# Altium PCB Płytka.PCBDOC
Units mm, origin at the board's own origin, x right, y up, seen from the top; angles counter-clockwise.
Board outline 97 x 97 mm, 2 copper layers (TopLayer, BottomLayer); 28 components, 0 nets, 155 pads, 1 vias.
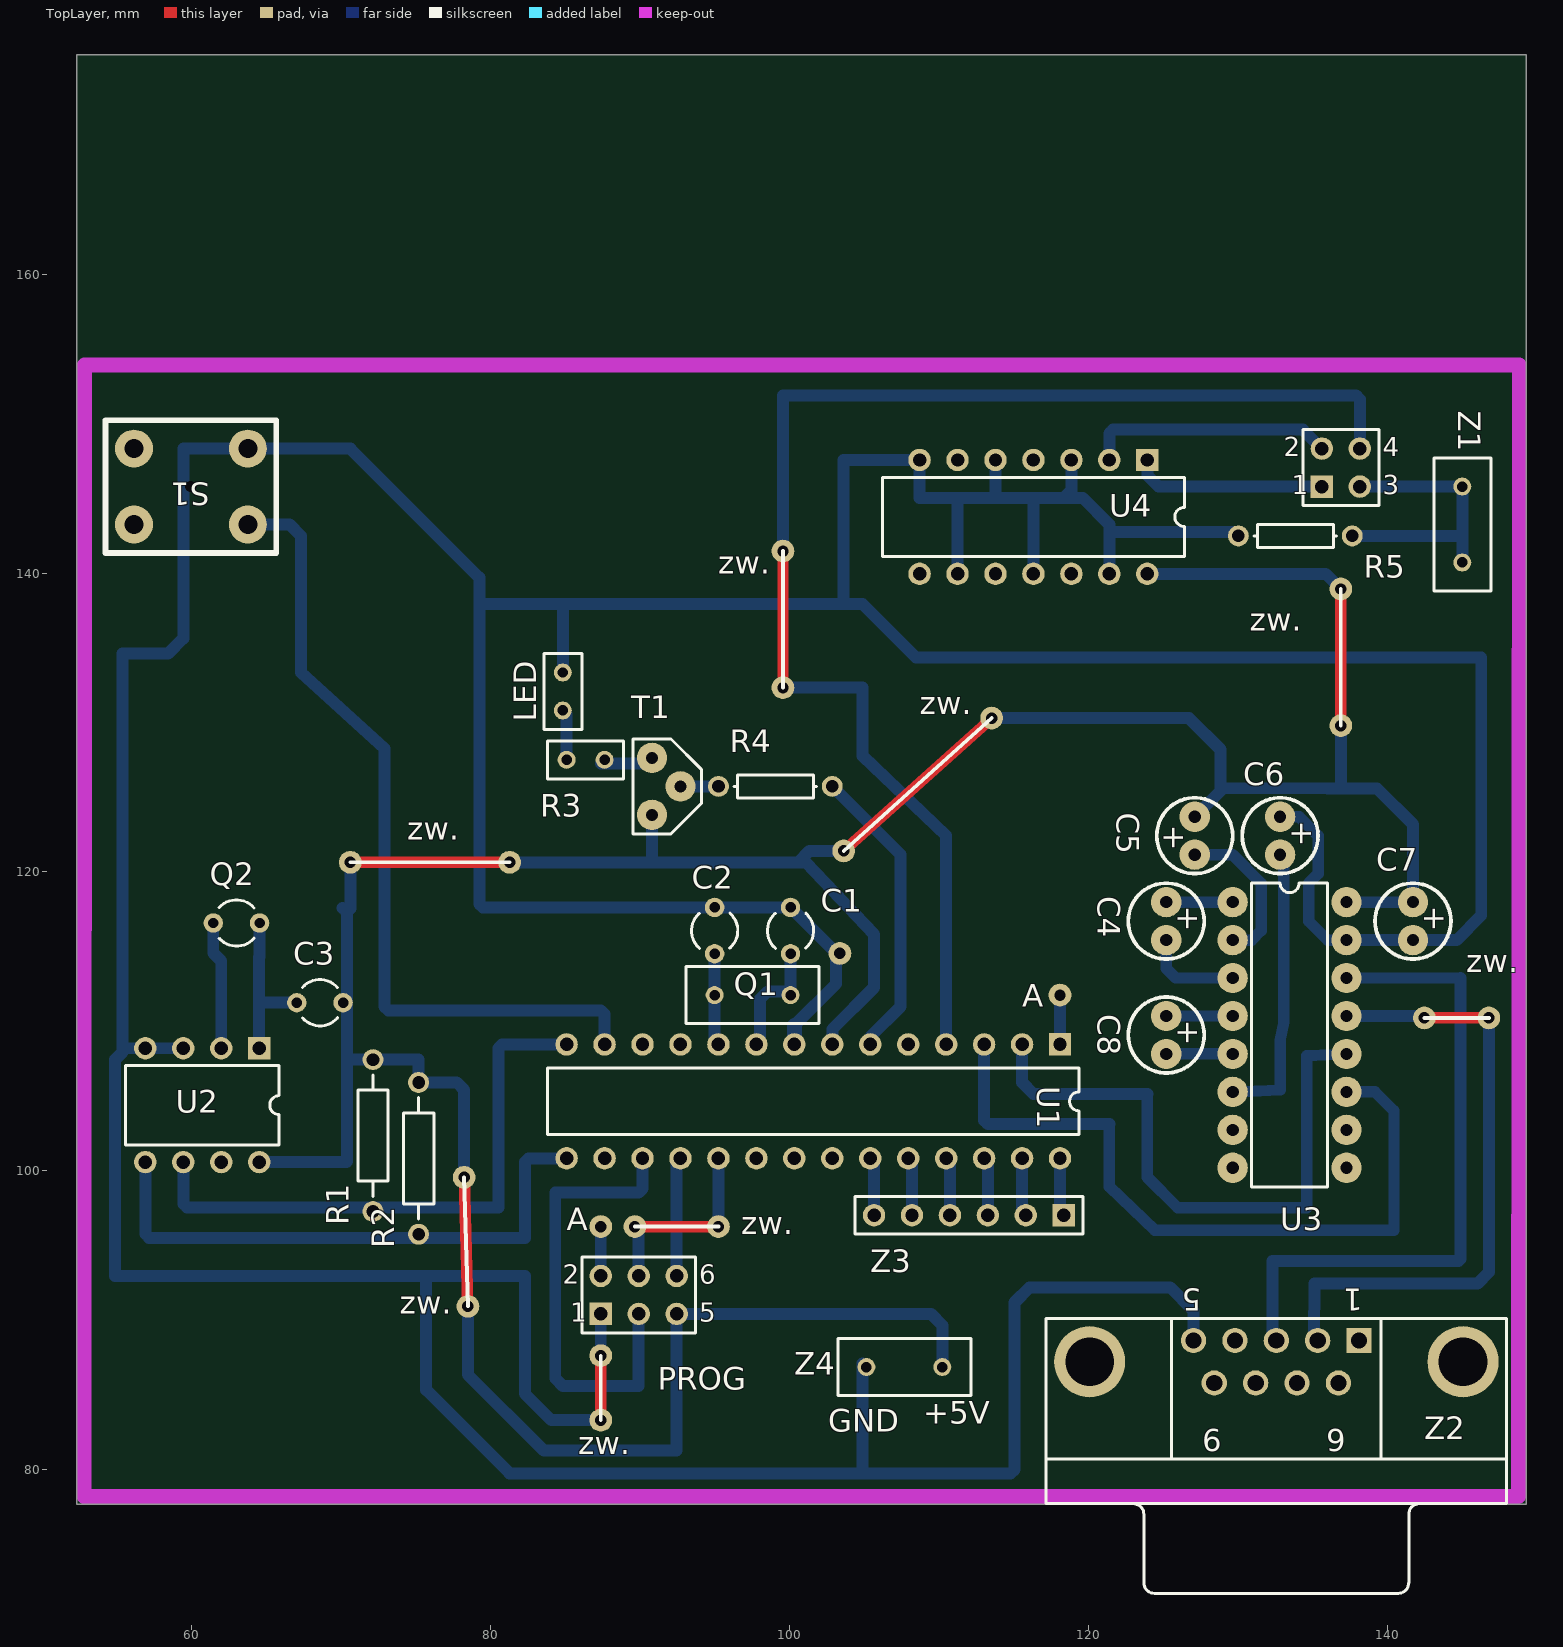
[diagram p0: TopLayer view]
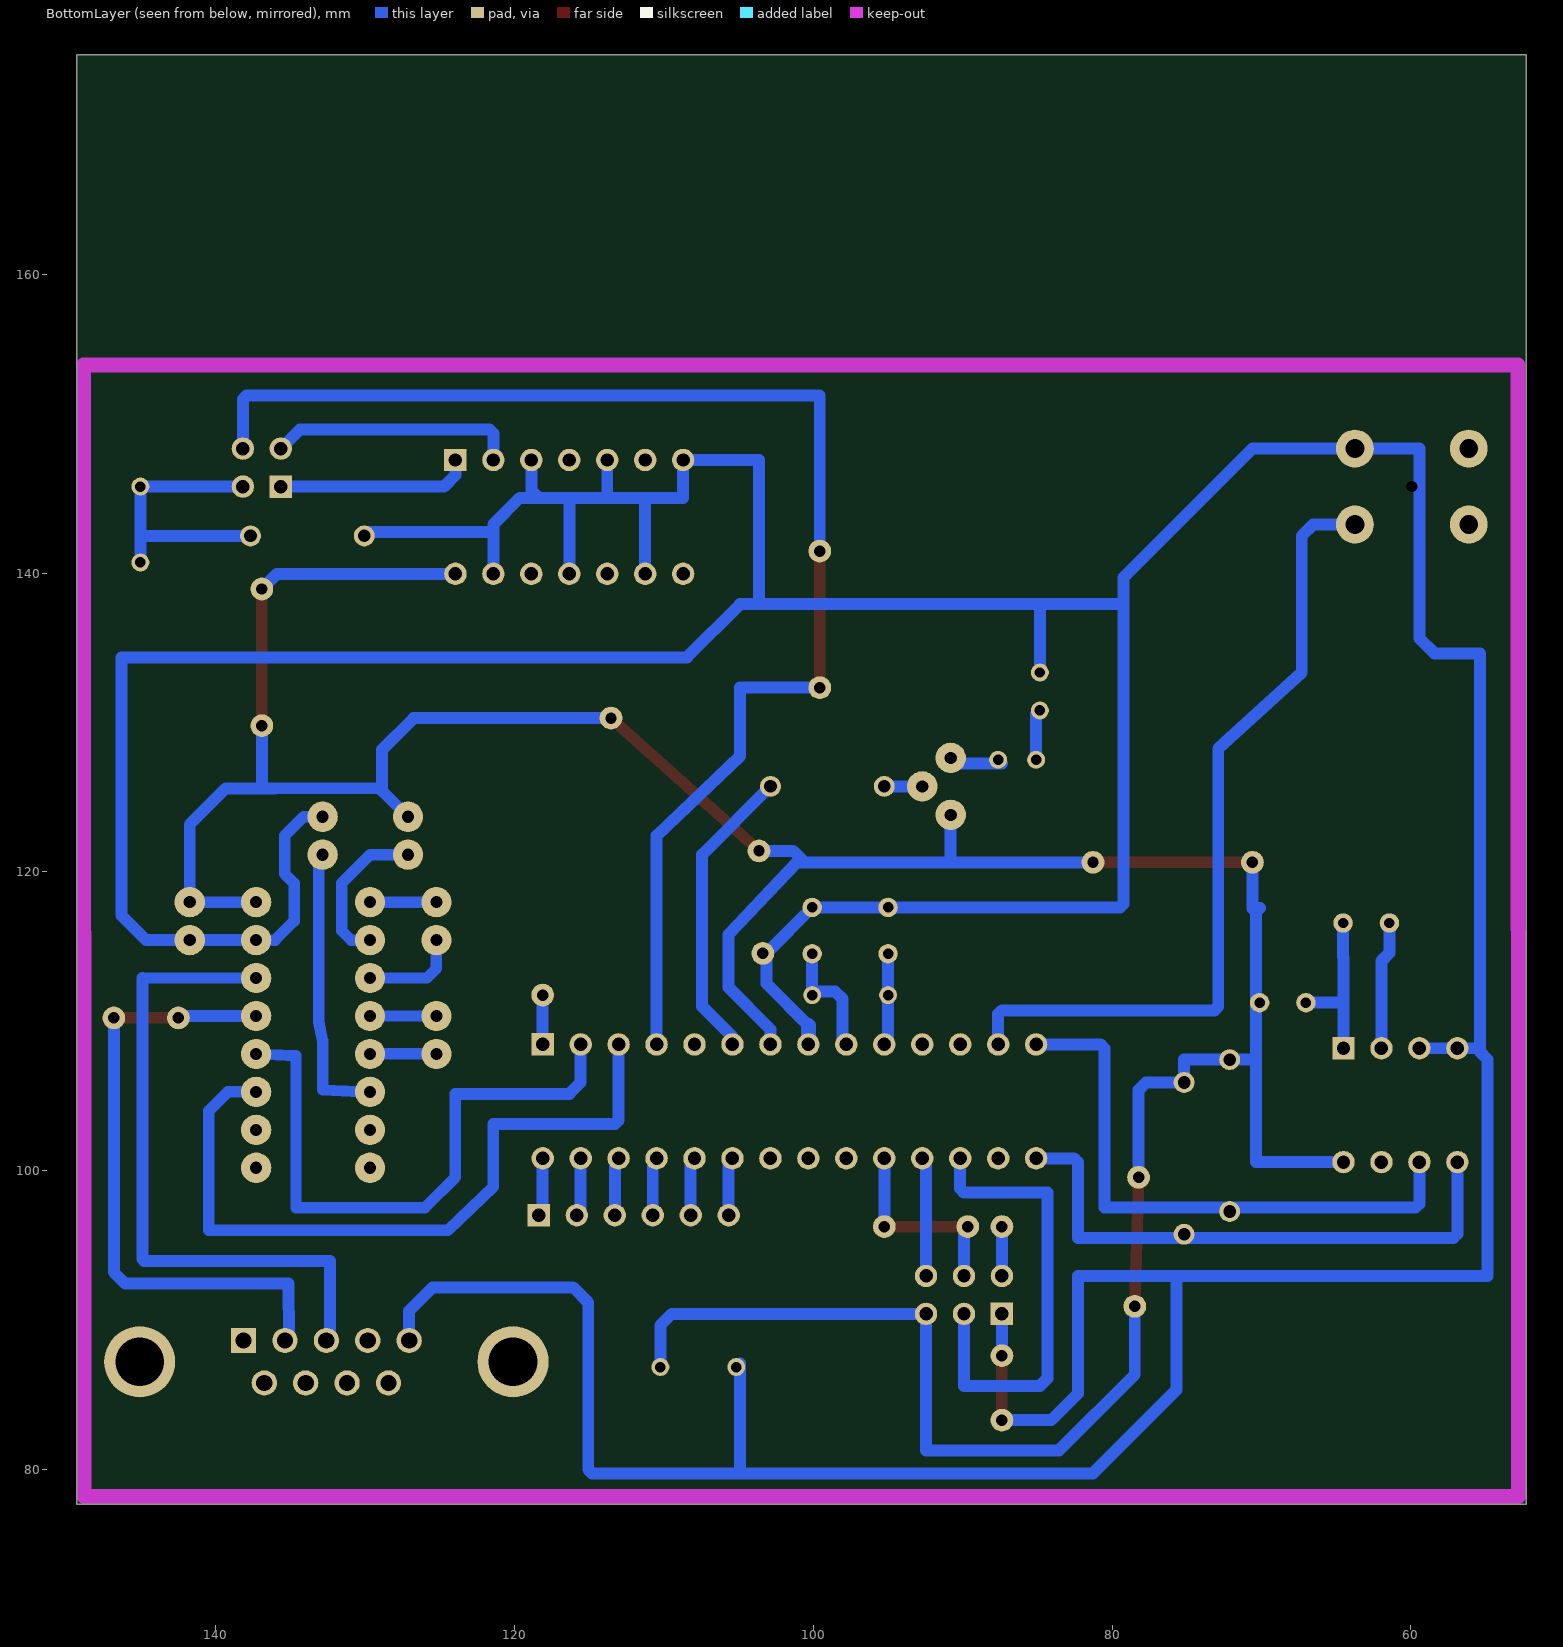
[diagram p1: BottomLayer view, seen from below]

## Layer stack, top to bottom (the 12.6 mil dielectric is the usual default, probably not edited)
TopLayer: signal copper 0.0356
Dielectric: core 0.32, FR-4, Dk 4.8
BottomLayer: signal copper 0.0356

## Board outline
52.3,77.7 149.3,77.7 149.3,174.7 52.3,174.7

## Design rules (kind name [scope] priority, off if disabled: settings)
Clearance [All] p1: gap=1
ComponentClearance [All] p1: gap=0.254 collisioncheckmode=0
PasteMaskExpansion PasteMaskExpansion_1 [All] p2: expansion=0
PlaneClearance PlaneClearance_1 [All] p1: clearance=0.508
PlaneClearance [All] p2: clearance=0.254
PolygonConnect [All] p1: connectstyle=Relief reliefconductorwidth=0.254 reliefentries=4 polygonreliefangle="90 Angle"
RoutingVias [All] p1: holewidth=1 width=3 viastyle="Through Hole" minholewidth=0.711 minwidth=1.27 maxholewidth=0.711 maxwidth=1.27
ShortCircuit ShortCircuit_1 [All] p2: allowed=FALSE
SolderMaskExpansion SolderMaskExpansion_1 [All] p1: expansion=0.102
SolderMaskExpansion [All] p2: expansion=0.051
TestPointUsage [All] p1: valid=0 allowmultiple=FALSE
Testpoint [All] p1: side=7 testpointundercomponent=TRUE minsize=1.016 maxsize=2.54 preferedsize=1.524 minholesize=0.508 maxholesize=1.016 preferedholesize=0.813 testpointgrid=0.025 style=1001 order=-539222988
UnRoutedNet UnRoutedNet_1 [All] p2:
Width [All] p1: maxlimit=1 minlimit=0.8 preferedwidth=0.254 toplayer_minwidth=1 toplayer_prefwidth=1 bottomlayer_prefwidth=0.8 minimp=50.000000 maximp=50.000000 favimp=50.000000
16 further rules are at their usual default settings.

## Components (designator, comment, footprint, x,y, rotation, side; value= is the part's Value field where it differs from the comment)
C1 "Comment" BCY-W2/D3.1 100.076,116.078 r0 top
C2 "Comment" BCY-W2/D3.1 94.996,116.078 r0 top
C3 "Comment" BCY-W2/D3.1 68.58,111.252 r90 top
C4 "" CE5#1 125.222,117.983 r270 top locked
C5 "" CE5#2 127.127,121.158 r270 top locked
C6 "" CE5#1 132.842,123.698 r270 top locked
C7 "" CE5#1 141.732,117.983 r270 top locked
C8 "" CE5#1 125.222,110.363 r270 top locked
LED "BC557" RAD-0.1 84.836,132.08 r270 top
PROG "BC557" HDR2X3 87.376,90.424 r0 top
Q1 "Comment" RAD-0.2 100.076,111.76 r180 top
Q2 "Comment" BCY-W2/D3.1 62.992,116.586 r90 top
R1 "Comment" AXIAL-0.4 72.136,102.362 r90 top
R2 "Comment" AXIAL-0.4 75.184,100.838 r90 top
R3 "BC557" RAD-0.1 86.36,127.508 r0 top
R4 "BC557" AXIAL-0.3 99.06,125.73 r0 top
R5 "BC557" AXIAL-0.3 133.858,142.494 r0 top
S1 "" PRZ1 59.944,145.796 r180 top
T1 "" T 90.805,123.825 r90 top locked
U1 "Comment" DIP-28/E5.3 101.6,104.648 r180 top
U2 "Comment" DIP-8 60.706,104.394 r180 top
U3 "" U16 129.667,117.983 r270 top locked
U4 "BC557" DIP-14 116.332,143.764 r180 top
Z1 "Comment" RAD-0.2 145.034,145.796 r270 top
Z2 "BC557" DSUB1.385-2H9 132.588,77.724 r180 top
Z3 "BC557" HDR1X6 118.364,97.028 r180 top
Z4 "Comment" RAD-0.2 105.156,86.868 r0 top
? "BC557" HDR2X2 135.636,145.796 r0 top

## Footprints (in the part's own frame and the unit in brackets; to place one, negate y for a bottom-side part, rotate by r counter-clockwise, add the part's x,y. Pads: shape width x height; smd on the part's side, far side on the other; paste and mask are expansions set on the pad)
AXIAL-0.3 [mm]
  round 1.4 hole 0.85: 1(-3.81,0) 2(3.81,0)
  silkscreen extent -2.77,-0.76 2.77,0.76
AXIAL-0.4 [mm]
  round 1.4 hole 0.85: 1(-5.08,0) 2(5.08,0)
  silkscreen extent -4.06,-1.02 4.06,1.02
BCY-W2/D3.1 [mm]
  round 1.3 hole 0.7: 1(0,1.55) 2(0,-1.55)
  silkscreen extent -1.55,-1.19 1.55,1.17
CE5#1 [mil]
  round 80 hole 32: 1(0,0) 2(100,0)
  silkscreen extent -50,-100 150,100
CE5#2 [mil]
  round 80 hole 32: 1(0,0) 2(-100,0)
  silkscreen extent -150,-100 50,100
DIP-8 [mm]
  rect 1.5x1.5 hole 0.9: 1(-3.81,-3.81)
  round 1.5 hole 0.9: 2(-1.27,-3.81) 3(1.27,-3.81) 4(3.81,-3.81) 5(3.81,3.81) 6(1.27,3.81) 7(-1.27,3.81) 8(-3.81,3.81)
  silkscreen extent -5.15,-2.65 5.15,2.65
DIP-14 [mm]
  rect 1.5x1.5 hole 0.9: 1(-7.62,-3.81)
  round 1.5 hole 0.9: 2(-5.08,-3.81) 3(-2.54,-3.81) 4(0,-3.81) 5(2.54,-3.81) 6(5.08,-3.81) 7(7.62,-3.81) 8(7.62,3.81) 9(5.08,3.81) 10(2.54,3.81) 11(0,3.81) 12(-2.54,3.81) 13(-5.08,3.81) 14(-7.62,3.81)
  silkscreen extent -10.1,-2.65 10.1,2.65
DIP-28/E5.3 [mm]
  rect 1.5x1.5 hole 0.9: 1(-16.51,-3.81)
  round 1.5 hole 0.9: 2(-13.97,-3.81) 3(-11.43,-3.81) 4(-8.89,-3.81) 5(-6.35,-3.81) 6(-3.81,-3.81) 7(-1.27,-3.81) 8(1.27,-3.81) 9(3.81,-3.81) 10(6.35,-3.81) 11(8.89,-3.81) 12(11.43,-3.81) 13(13.97,-3.81) 14(16.51,-3.81) 15(16.51,3.81) 16(13.97,3.81) 17(11.43,3.81) 18(8.89,3.81) 19(6.35,3.81) 20(3.81,3.81) 21(1.27,3.81) 22(-1.27,3.81) 23(-3.81,3.81) 24(-6.35,3.81) 25(-8.89,3.81) 26(-11.43,3.81) 27(-13.97,3.81) 28(-16.51,3.81)
  silkscreen extent -17.78,-2.23 17.78,2.23
DSUB1.385-2H9 [mm] "Connector; D Subminiature; 9 Position; Right Angle; Pitch 1.385 mm"
  rect 1.69x1.69 hole 1.09: 1(-5.54,-10.92)
  round 1.69 hole 1.09: 2(-2.77,-10.92) 3(0,-10.92) 4(2.77,-10.92) 5(5.54,-10.92) 6(-4.155,-8.08) 7(-1.385,-8.08) 8(1.385,-8.08) 9(4.155,-8.08)
  round 4.76 hole 3.26: 10(-12.495,-9.5) 11(12.495,-9.5)
  silkscreen extent -15.4,-12.4 15.4,6
HDR1X6 [mm] "Connector; Header; 6 Position"
  rect 1.5x1.5 hole 0.9: 1(0,0)
  round 1.5 hole 0.9: 2(2.54,0) 3(5.08,0) 4(7.62,0) 5(10.16,0) 6(12.7,0)
  silkscreen extent -1.27,-1.27 13.97,1.27
HDR2X2 [mm] "Connector; Header; 2x2 Position"
  rect 1.5x1.5 hole 0.9: 1(0,0)
  round 1.5 hole 0.9: 2(0,2.54) 3(2.54,0) 4(2.54,2.54)
  silkscreen extent -1.27,-1.27 3.81,3.81
HDR2X3 [mm] "Connector; Header; 3x2 Position"
  rect 1.5x1.5 hole 0.9: 1(0,0)
  round 1.5 hole 0.9: 2(0,2.54) 3(2.54,0) 4(2.54,2.54) 5(5.08,0) 6(5.08,2.54)
  silkscreen extent -1.27,-1.27 6.35,3.81
PRZ1 [mm]
  round 2.54 hole 1.27: 0(-3.81,-2.54) 0(-3.81,2.54) 1(3.81,-2.54) 2(3.81,2.54)
  silkscreen extent -5.72,-4.45 5.72,4.45
RAD-0.1 [mm]
  round 1.2 hole 0.7: 1(-1.27,0) 2(1.27,0)
  silkscreen extent -2.54,-1.27 2.54,1.27
RAD-0.2 [mm]
  round 1.2 hole 0.7: 1(0,0) 2(5.08,0)
  silkscreen extent -1.91,-1.91 6.98,1.91
T [mil]
  round 80 hole 32: 1(0,0) 2(75,-75) 3(150,0)
  silkscreen extent -50,-130 200,50
U16 [mil]
  round 80 hole 32: 1(0,0) 2(100,0) 3(200,0) 4(300,0) 5(400,0) 6(500,0) 7(600,0) 8(700,0) 9(700,300) 10(600,300) 11(500,300) 12(400,300) 13(300,300) 14(200,300) 15(100,300) 16(0,300)
  silkscreen extent -50,50 750,250

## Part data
C1 C2 C3 Q2: library part XTAL
Z2: library part "D Connector 9"
?: library part "Header 2X2"

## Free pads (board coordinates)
  round 1.524 hole 0.762: 0(95.25,96.266) 1(89.662,96.266) 3(87.376,87.63) 4(78.232,99.568) 4(78.486,90.932) 4(87.376,83.312) 5(87.376,96.266) 6(118.11,111.76) 7(142.494,110.236) 8(146.812,110.236) 13(99.568,132.334) 14(99.568,141.478) 17(70.612,120.65) 18(81.28,120.65) 19(136.906,129.794) 20(136.906,138.938) 21(103.632,121.412) 22(113.538,130.302) 66(103.378,114.554)

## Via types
v1: diameter 0.508, hole 0.762, TopLayer to BottomLayer, 1 vias

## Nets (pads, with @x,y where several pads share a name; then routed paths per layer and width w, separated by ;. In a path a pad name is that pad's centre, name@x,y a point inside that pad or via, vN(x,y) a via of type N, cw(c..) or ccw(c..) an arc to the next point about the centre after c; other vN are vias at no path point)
pads on no net: ?.1 ?.2 ?.3 ?.4 C1.1 C1.2 C2.1 C2.2 C3.1 C3.2 C4.1 C4.2 C5.1 C5.2 C6.1 C6.2 C7.1 C7.2 C8.1 C8.2 LED.1 LED.2 PROG.1 PROG.2 PROG.3 PROG.4 PROG.5 PROG.6 Q1.1 Q1.2 Q2.1 Q2.2 R1.1 R1.2 R2.1 R2.2 R3.1 R3.2 R4.1 R4.2 R5.1 R5.2 S1.0 S1.1 S1.2 T1.1 T1.2 T1.3 U1.1 U1.2 U1.3 U1.4 U1.5 U1.6 U1.7 U1.8 U1.9 U1.10 U1.11 U1.12 U1.13 U1.14 U1.15 U1.16 U1.17 U1.18 U1.19 U1.20 U1.21 U1.22 U1.23 U1.24 U1.25 U1.26 U1.27 U1.28 U2.1 U2.2 U2.3 U2.4 U2.5 U2.6 U2.7 U2.8 U3.1 U3.2 U3.3 U3.4 U3.5 U3.6 U3.7 U3.8 U3.9 U3.10 U3.11 U3.12 U3.13 U3.14 U3.15 U3.16 U4.1 U4.2 U4.3 U4.4 U4.5 U4.6 U4.7 U4.8 U4.9 U4.10 U4.11 U4.12 U4.13 U4.14 Z1.1 Z1.2 Z2.1 Z2.2 Z2.3 Z2.4 Z2.5 Z2.6 Z2.7 Z2.8 Z2.9 Z2.10 Z2.11 Z3.1 Z3.2 Z3.3 Z3.4 Z3.5 Z3.6 Z4.1 Z4.2
copper on no net: | length 1332.7
  TopLayer w0.762: 70.612,120.65 81.28,120.65 ; 78.232,99.568 78.486,90.932 ; 87.376,83.312 87.376,87.63 ; 89.662,96.266 95.25,96.266 ; 99.568,132.334 99.568,141.478 ; 103.632,121.412 113.538,130.302 ; 136.906,129.794 136.906,138.938 ; 142.494,110.236 146.812,110.236
  BottomLayer w0.762: 90.805,123.19 90.805,123.825 ; 121.412,103.124 121.412,100.838 121.412,98.933 124.46,96.012 131.826,96.012 135.636,96.012 140.462,96.012 140.462,97.028 140.462,98.298 140.462,104.013 139.192,105.283 137.287,105.283 ; 123.952,105.156 123.952,99.568 125.984,97.536 134.62,97.536 134.62,102.108 134.62,106.426 134.62,107.696 137.287,107.823 ; 125.222,107.823 129.667,107.823 ; 125.222,110.363 129.667,110.363 ; 125.222,115.443 125.222,113.538 125.857,112.903 129.667,112.903 ; 125.222,117.983 129.667,117.983 ; 127.127,121.158 129.667,121.158 131.572,119.253 131.572,116.078 130.937,115.443 129.667,115.443 ; 127.127,123.698 129.032,125.603 136.017,125.603 ; 129.667,105.283 130.302,105.283 132.842,105.41 132.842,108.712 133.096,109.982 133.096,121.412 ; 132.842,123.698 134.112,123.698 135.382,122.428 135.382,119.888 134.747,119.253 134.747,116.713 136.017,115.443 137.287,115.443 ; 137.287,112.903 144.907,112.903 ; 137.287,117.983 141.732,117.983
  BottomLayer w0.8: 55.372,122.174 55.372,134.62 57.404,134.62 58.42,134.62 59.436,135.636 59.436,148.336 60.96,148.336 63.754,148.336 70.612,148.336 79.248,139.7 79.248,139.446 79.248,117.856 79.476,117.628 94.996,117.628 100.076,117.628 103.124,114.58 103.124,112.522 100.33,109.728 ; 55.372,122.428 55.372,109.728 55.372,108.204 ; 56.896,95.758 56.896,100.584 ; 57.15,95.504 61.214,95.504 ; 58.928,95.504 81.788,95.504 82.296,95.504 82.296,100.584 82.55,100.838 85.09,100.838 ; 59.436,97.79 59.436,100.584 ; 59.436,108.204 55.372,108.204 ; 59.69,97.536 63.754,97.536 ; 61.442,116.586 61.442,114.58 61.976,114.046 61.976,108.204 ; 61.468,97.536 80.518,97.536 80.518,104.902 80.518,108.204 80.772,108.458 85.09,108.458 ; 63.754,143.256 66.548,143.256 67.31,142.494 67.31,133.35 72.898,128.27 72.898,112.268 72.898,110.998 73.152,110.744 87.376,110.744 87.63,110.49 87.63,108.458 ; 64.516,108.204 64.516,114.3 64.542,114.326 64.542,116.586 ; 64.516,111.506 64.77,111.252 67.03,111.252 ; 64.77,100.584 70.358,100.584 70.384,100.61 70.384,112.522 70.384,117.322 70.104,117.602 ; 70.384,107.442 73.66,107.442 75.184,107.442 75.184,105.918 77.724,105.918 78.232,105.41 78.232,99.568 ; 70.612,117.55 70.612,120.65 ; 75.692,92.964 75.692,85.344 81.28,79.756 114.808,79.756 115.062,80.01 115.062,91.186 116.078,92.202 125.476,92.202 127.048,90.63 127.048,88.644 ; 78.486,90.932 78.486,86.36 83.566,81.28 92.456,81.28 92.456,90.424 109.474,90.424 110.236,89.662 110.236,86.868 ; 79.248,137.922 85.09,137.922 ; 81.28,120.65 90.17,120.65 90.678,120.65 ; 84.836,130.81 85.09,130.556 85.09,127.508 ; 84.836,133.35 84.836,137.922 88.646,137.922 92.71,137.922 101.092,137.922 101.6,137.922 104.902,137.922 108.458,134.366 117.348,134.366 ; 87.376,83.312 84.074,83.312 82.296,85.09 82.296,90.678 82.296,92.964 54.864,92.964 54.864,107.442 55.372,107.95 55.372,108.204 ; 87.376,87.63 87.376,90.424 ; 87.376,92.964 87.376,96.266 ; 87.376,127.254 90.424,127.254 90.805,127.635 ; 89.662,96.266 89.916,96.012 89.916,92.964 ; 89.916,90.424 89.916,85.598 84.836,85.598 84.328,86.106 84.328,98.552 89.916,98.552 90.17,98.806 90.17,100.838 ; 90.805,123.444 90.805,120.777 90.678,120.65 ; 92.456,92.964 92.456,100.584 92.71,100.838 ; 92.964,125.73 95.25,125.73 ; 94.996,114.528 94.996,110.49 94.996,108.712 95.25,108.458 95.25,108.712 ; 95.25,96.266 95.25,100.838 ; 97.536,108.458 97.79,108.458 98.044,108.712 98.044,111.506 98.552,112.014 100.076,112.014 ; 99.568,132.334 104.902,132.334 104.902,127.762 110.49,122.428 110.49,119.38 110.49,119.126 110.49,108.458 ; 99.568,141.478 99.568,151.892 121.158,151.892 137.922,151.892 138.176,151.638 138.176,148.336 ; 100.076,111.76 100.076,114.528 ; 100.584,120.65 101.346,121.412 103.632,121.412 ; 102.87,108.458 102.87,109.474 105.664,112.268 105.664,115.824 101.092,120.65 90.678,120.65 ; 102.87,125.73 107.442,121.158 107.442,110.998 105.41,108.966 105.41,108.458 ; 103.632,137.922 103.632,147.574 108.712,147.574 108.712,145.034 113.792,145.034 ; 104.902,79.756 104.902,87.122 ; 105.41,100.838 105.664,100.584 105.664,97.028 ; 107.95,100.838 108.204,100.584 108.204,97.028 ; 110.49,100.838 110.744,100.584 110.744,97.028 ; 111.252,139.954 111.252,144.78 ; 113.03,100.838 113.284,100.584 113.284,97.028 ; 113.03,108.458 113.03,103.378 113.284,103.124 121.412,103.124 ; 113.538,130.302 126.746,130.302 128.851,128.197 128.851,125.422 ; 113.792,147.574 113.792,145.034 ; 115.57,97.282 115.57,100.838 ; 115.57,108.458 115.57,105.918 116.332,105.156 123.952,105.156 ; 116.332,139.954 116.332,144.78 116.586,145.034 ; 117.094,134.366 123.444,134.366 146.304,134.366 146.304,117.094 144.653,115.443 141.732,115.443 137.287,115.443 ; 118.11,100.838 118.11,97.282 ; 118.11,108.458 118.11,111.76 ; 118.364,97.282 118.364,97.028 ; 118.872,147.574 118.872,145.542 118.364,145.034 ; 121.412,139.954 121.412,143.256 119.634,145.034 118.364,145.034 ; 121.412,142.748 129.794,142.748 130.048,142.494 ; 121.412,147.574 121.412,149.352 121.666,149.606 134.366,149.606 135.636,148.336 ; 123.952,139.954 135.89,139.954 136.906,138.938 ; 123.952,147.574 123.952,146.558 124.714,145.796 135.636,145.796 ; 132.334,88.898 132.334,93.98 144.78,93.98 144.907,94.107 144.907,112.903 ; 135.104,88.898 135.128,92.456 135.334,92.456 146.05,92.456 146.812,93.218 146.812,110.236 ; 136.017,125.603 139.319,125.603 141.732,123.19 141.732,117.983 ; 136.906,125.603 136.906,129.794 ; 137.287,110.363 142.367,110.363 ; 137.922,142.494 145.034,142.494 ; 138.176,145.796 145.034,145.796 145.034,140.716 ; 113.792,145.034 118.364,145.034 ; 118.11,97.282 118.364,97.028 ; 118.11,97.282 118.364,97.028
  BottomLayer w1: 100.33,108.458 100.33,109.728
  other v1: 59.944,145.796

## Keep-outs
KeepOutLayer:
  lines w1: 52.8,78.2 148.8,78.2 148.844,153.924 52.832,153.924 52.8,78.2

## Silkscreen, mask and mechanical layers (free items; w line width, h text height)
TopOverlay:
  lines w0.254: 70.612,120.65 81.28,120.65 ; 78.232,99.568 78.486,90.932 ; 87.376,83.312 87.376,87.63 ; 89.662,96.266 95.25,96.266 ; 99.568,132.334 99.568,141.478 ; 103.632,121.412 113.538,130.302 ; 136.906,129.794 136.906,138.938 ; 142.494,110.236 146.812,110.236
  text "zw." at 95.25,139.954 h1.52
  text "zw." at 130.81,136.144 h1.52
  text "zw." at 108.712,130.556 h1.52
  text "zw." at 74.422,122.174 h1.52
  text "zw." at 145.288,113.284 h1.52
  text "A" at 115.57,110.998 h1.52
  text "A" at 85.09,96.012 h1.52
  text "zw." at 96.774,95.758 h1.52
  text "zw." at 73.914,90.424 h1.52
  text "+5V" at 108.966,83.058 h1.52
  text "GND" at 102.616,82.55 h1.52
  text "zw." at 85.852,81.026 h1.52
Mechanical4:
  lines w1: 50.8,76.2 150.8,76.2 150.876,155.702 50.8,155.702 50.8,76.2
